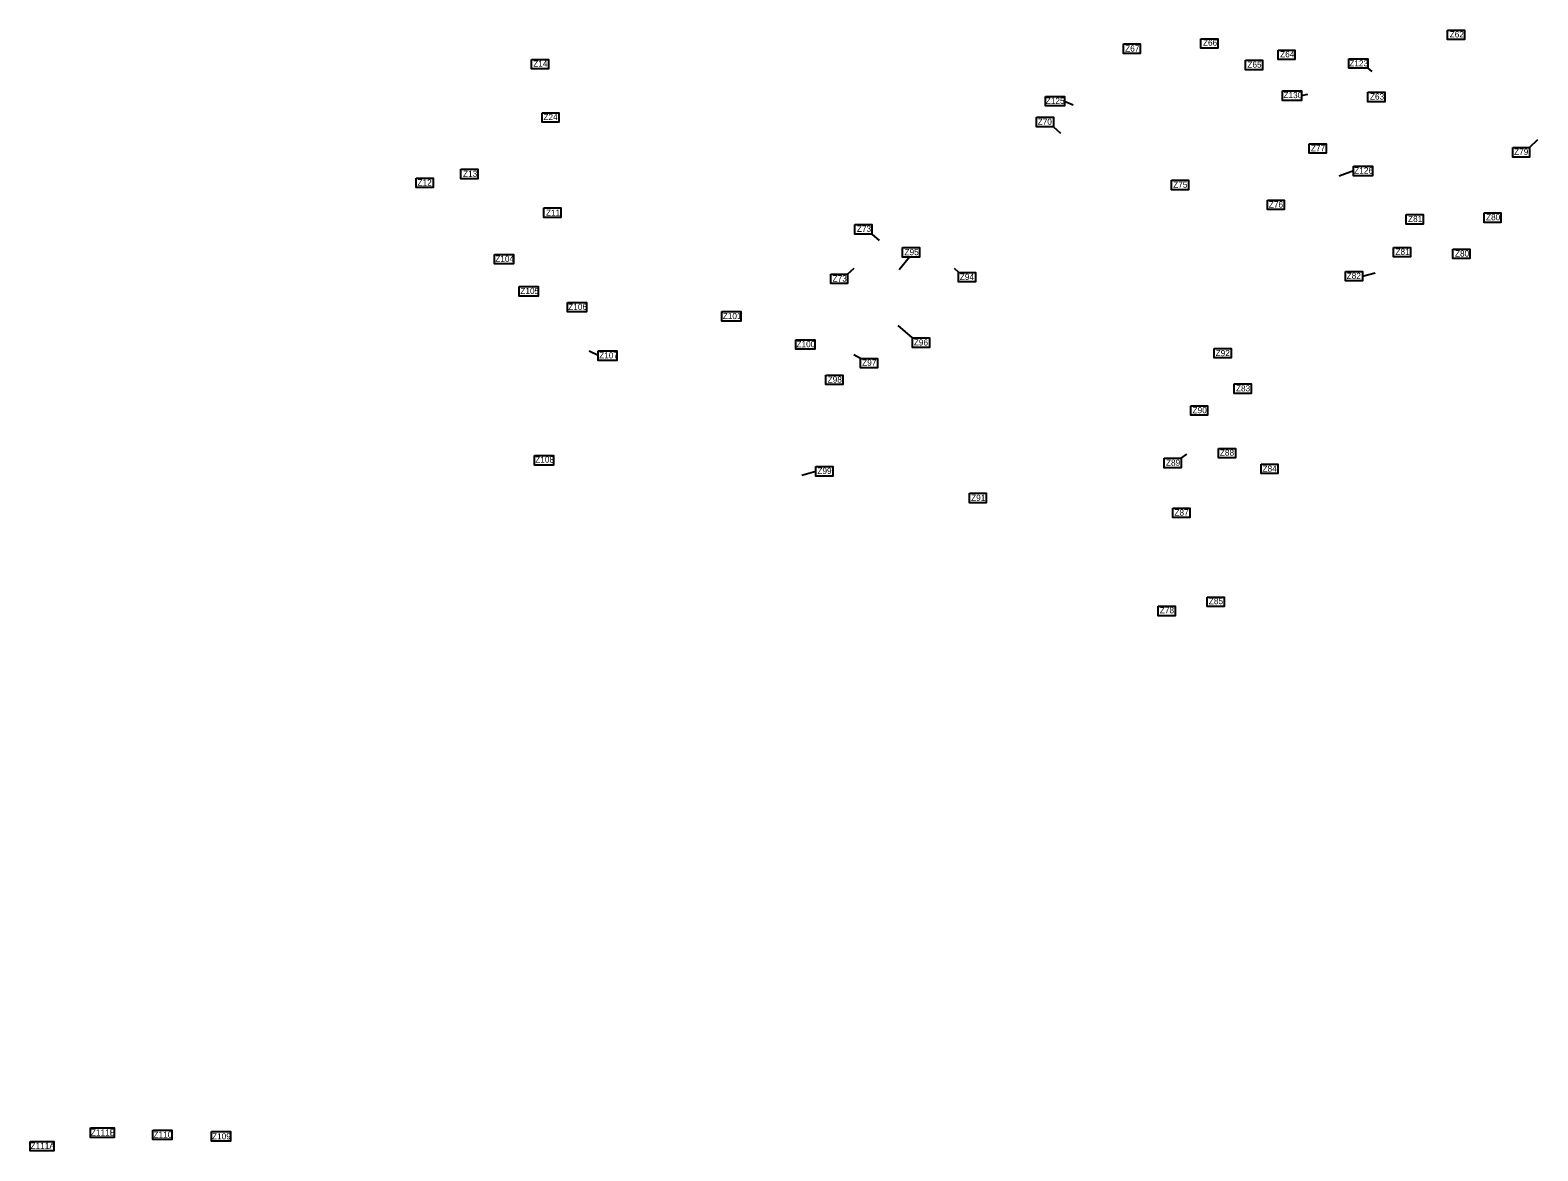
# Model space of a CAD drawing. Extents: x -443485 to -434416, y -1135265 to -1129797.
# Drawn here: x -443485 to -441040, y -1133468 to -1131650 of the extents above; entities that cross this region are included whole.
import ezdxf

# ---------------------------------------------------------------- set-up
doc = ezdxf.new("R2010")
doc.units = 0
doc.layers.add('Vrstva 3', color=7, linetype='Continuous')
doc.layers.add('Vrstva 8', color=7, linetype='Continuous')

msp = doc.modelspace()

# ---------------------------------------------------------------- linework, layer by layer
at = {"layer": 'Vrstva 3'}
for p, q in [((-441825.2, -1131807.1), (-441813.8, -1131817.4)), ((-441052.9, -1131840.8), (-441039.6, -1131827.8)), ((-442119.8, -1131981.1), (-442108.1, -1131991.8)), ((-442058.5, -1132018.5), (-442075.2, -1132039)), ((-442159, -1132046), (-442148.7, -1132036.3)), ((-441979.2, -1132043), (-441985.6, -1132037)), ((-441324.1, -1132049.4), (-441303.6, -1132044)), ((-442053.6, -1132149.7), (-442077, -1132129.5)), ((-442563.8, -1132178.3), (-442578.2, -1132171.1)), ((-442137.9, -1132182.9), (-442149.2, -1132176.8)), ((-441618.1, -1132344.9), (-441608.8, -1132338.2)), ((-442210.4, -1132366.1), (-442233.5, -1132372.9))]:
    msp.add_line(p, q, dxfattribs=at)
for points in [[(-441186, -1131650.3), (-441158.6, -1131650.3), (-441158.6, -1131665.7), (-441186, -1131665.7)], [(-441711.8, -1131672.7), (-441684.5, -1131672.7), (-441684.5, -1131688.1), (-441711.8, -1131688.1)], [(-441586.1, -1131664.3), (-441558.7, -1131664.3), (-441558.7, -1131679.7), (-441586.1, -1131679.7)], [(-441460.9, -1131682.5), (-441433.5, -1131682.5), (-441433.5, -1131697.9), (-441460.9, -1131697.9)], [(-442671.7, -1131697.8), (-442644.4, -1131697.8), (-442644.4, -1131713.2), (-442671.7, -1131713.2)], [(-441513.5, -1131699.1), (-441486.1, -1131699.1), (-441486.1, -1131714.5), (-441513.5, -1131714.5)], [(-441315.3, -1131751.1), (-441287.9, -1131751.1), (-441287.9, -1131766.5), (-441315.3, -1131766.5)], [(-442654.5, -1131784.2), (-442627.2, -1131784.2), (-442627.2, -1131799.6), (-442654.5, -1131799.6)], [(-441852.6, -1131791.7), (-441825.2, -1131791.7), (-441825.2, -1131807.1), (-441852.6, -1131807.1)], [(-441410.4, -1131834.5), (-441383, -1131834.5), (-441383, -1131849.9), (-441410.4, -1131849.9)], [(-441080.2, -1131840.8), (-441052.9, -1131840.8), (-441052.9, -1131856.2), (-441080.2, -1131856.2)], [(-442786.3, -1131876), (-442759, -1131876), (-442759, -1131891.4), (-442786.3, -1131891.4)], [(-442858.8, -1131890.4), (-442831.4, -1131890.4), (-442831.4, -1131905.8), (-442858.8, -1131905.8)], [(-441633.7, -1131893.9), (-441606.4, -1131893.9), (-441606.4, -1131909.3), (-441633.7, -1131909.3)], [(-441478.3, -1131925.9), (-441450.9, -1131925.9), (-441450.9, -1131941.3), (-441478.3, -1131941.3)], [(-442651.8, -1131938.6), (-442624.4, -1131938.6), (-442624.4, -1131954), (-442651.8, -1131954)], [(-441253, -1131949.4), (-441225.6, -1131949.4), (-441225.6, -1131964.8), (-441253, -1131964.8)], [(-441126.7, -1131946.9), (-441099.4, -1131946.9), (-441099.4, -1131962.3), (-441126.7, -1131962.3)], [(-442147.2, -1131965.7), (-442119.8, -1131965.7), (-442119.8, -1131981.1), (-442147.2, -1131981.1)], [(-441273.5, -1132002.7), (-441246.1, -1132002.7), (-441246.1, -1132018.1), (-441273.5, -1132018.1)], [(-442731.9, -1132014.2), (-442701.2, -1132014.2), (-442701.2, -1132029.6), (-442731.9, -1132029.6)], [(-442069.8, -1132003.1), (-442042.5, -1132003.1), (-442042.5, -1132018.5), (-442069.8, -1132018.5)], [(-441177.4, -1132005.6), (-441150, -1132005.6), (-441150, -1132021), (-441177.4, -1132021)], [(-442186.4, -1132046), (-442159, -1132046), (-442159, -1132061.4), (-442186.4, -1132061.4)], [(-441979.2, -1132043.3), (-441951.9, -1132043.3), (-441951.9, -1132058.7), (-441979.2, -1132058.7)], [(-441351.4, -1132041.7), (-441324.1, -1132041.7), (-441324.1, -1132057.1), (-441351.4, -1132057.1)], [(-442691.5, -1132066.2), (-442660.7, -1132066.2), (-442660.7, -1132081.6), (-442691.5, -1132081.6)], [(-442613.5, -1132092), (-442582.8, -1132092), (-442582.8, -1132107.4), (-442613.5, -1132107.4)], [(-442363, -1132106.9), (-442332.2, -1132106.9), (-442332.2, -1132122.3), (-442363, -1132122.3)], [(-442563.8, -1132170.6), (-442533.1, -1132170.6), (-442533.1, -1132186), (-442563.8, -1132186)], [(-442242.9, -1132152.5), (-442212.2, -1132152.5), (-442212.2, -1132167.9), (-442242.9, -1132167.9)], [(-442053.6, -1132149.7), (-442026.2, -1132149.7), (-442026.2, -1132165.1), (-442053.6, -1132165.1)], [(-441564.6, -1132166.6), (-441537.2, -1132166.6), (-441537.2, -1132182), (-441564.6, -1132182)], [(-442137.9, -1132182.9), (-442110.5, -1132182.9), (-442110.5, -1132198.2), (-442137.9, -1132198.2)], [(-442194.3, -1132209.9), (-442166.9, -1132209.9), (-442166.9, -1132225.3), (-442194.3, -1132225.3)], [(-441532.1, -1132224.2), (-441504.8, -1132224.2), (-441504.8, -1132239.6), (-441532.1, -1132239.6)], [(-441602.6, -1132259.7), (-441575.2, -1132259.7), (-441575.2, -1132275.1), (-441602.6, -1132275.1)], [(-442667.1, -1132340.5), (-442636.3, -1132340.5), (-442636.3, -1132355.9), (-442667.1, -1132355.9)], [(-441645.5, -1132344.9), (-441618.1, -1132344.9), (-441618.1, -1132360.3), (-441645.5, -1132360.3)], [(-441557.5, -1132329), (-441530.2, -1132329), (-441530.2, -1132344.4), (-441557.5, -1132344.4)], [(-442210.4, -1132358.4), (-442183, -1132358.4), (-442183, -1132373.8), (-442210.4, -1132373.8)], [(-441488.5, -1132354.4), (-441461.1, -1132354.4), (-441461.1, -1132369.8), (-441488.5, -1132369.8)], [(-441961.6, -1132401.7), (-441934.2, -1132401.7), (-441934.2, -1132417.1), (-441961.6, -1132417.1)], [(-441631.5, -1132425.8), (-441604.1, -1132425.8), (-441604.1, -1132441.2), (-441631.5, -1132441.2)], [(-441655.3, -1132585), (-441627.9, -1132585), (-441627.9, -1132600.4), (-441655.3, -1132600.4)], [(-441575.8, -1132570.2), (-441548.5, -1132570.2), (-441548.5, -1132585.5), (-441575.8, -1132585.5)], [(-443387, -1133431.3), (-443348.5, -1133431.3), (-443348.5, -1133446.7), (-443387, -1133446.7)], [(-443286.1, -1133434.8), (-443255.3, -1133434.8), (-443255.3, -1133450.2), (-443286.1, -1133450.2)], [(-443190.7, -1133437.1), (-443160, -1133437.1), (-443160, -1133452.5), (-443190.7, -1133452.5)], [(-443484.9, -1133453.1), (-443446.5, -1133453.1), (-443446.5, -1133468.5), (-443484.9, -1133468.5)]]:
    msp.add_lwpolyline(points, close=True, dxfattribs=at)
at = {"layer": 'Vrstva 8'}
for p, q in [((-441315.6, -1131712), (-441308.9, -1131717.3)), ((-441422.7, -1131756.5), (-441412.9, -1131754.3)), ((-441807.3, -1131765.5), (-441793.1, -1131771.6)), ((-441338.6, -1131878.7), (-441361.9, -1131887.4))]:
    msp.add_line(p, q, dxfattribs=at)
for points in [[(-441346.4, -1131696.6), (-441315.6, -1131696.6), (-441315.6, -1131712), (-441346.4, -1131712)], [(-441838.1, -1131757.8), (-441807.3, -1131757.8), (-441807.3, -1131773.2), (-441838.1, -1131773.2)], [(-441453.5, -1131748.8), (-441422.7, -1131748.8), (-441422.7, -1131764.2), (-441453.5, -1131764.2)], [(-441338.6, -1131871), (-441307.8, -1131871), (-441307.8, -1131886.4), (-441338.6, -1131886.4)]]:
    msp.add_lwpolyline(points, close=True, dxfattribs=at)

# ---------------------------------------------------------------- texts
at = {"layer": 'Vrstva 3'}
for s, p in [('Z62', (-441182.6, -1131662.1)), ('Z67', (-441708.9, -1131685)), ('Z66', (-441582.7, -1131675.6)), ('Z64', (-441457.5, -1131694.4)), ('Z14', (-442668.9, -1131709.6)), ('Z65', (-441510.7, -1131711.2)), ('Z63', (-441311.9, -1131762.9)), ('Z24', (-442652.4, -1131796.3)), ('Z70', (-441850.8, -1131803.9)), ('Z77', (-441407.6, -1131846.7)), ('Z79', (-441078.1, -1131852.6)), ('Z13', (-442782.8, -1131888.3)), ('Z12', (-442856.6, -1131902.5)), ('Z75', (-441631, -1131906)), ('Z76', (-441475.8, -1131938.1)), ('Z11', (-442648.3, -1131951.5)), ('Z81', (-441250.1, -1131961.6)), ('Z80', (-441123.6, -1131958.7)), ('Z73', (-442144, -1131977.5)), ('Z104', (-442730.5, -1132026.2)), ('Z95', (-442066.8, -1132015.4)), ('Z81', (-441270.5, -1132014.9)), ('Z80', (-441174, -1132017.7)), ('Z73', (-442183.4, -1132058.1)), ('Z94', (-441977.1, -1132055.6)), ('Z82', (-441349.6, -1132054)), ('Z105', (-442689.8, -1132078.4)), ('Z106', (-442612.2, -1132104.3)), ('Z101', (-442361.6, -1132119.1)), ('Z107', (-442562, -1132182.9)), ('Z100', (-442242, -1132164.7)), ('Z96', (-442051.7, -1132161.9)), ('Z92', (-441562.2, -1132179.2)), ('Z97', (-442135.5, -1132194.7)), ('Z98', (-442191.4, -1132222.2)), ('Z83', (-441529.2, -1132236.4)), ('Z90', (-441599.6, -1132271.8)), ('Z108', (-442665.7, -1132352)), ('Z88', (-441555.3, -1132340.8)), ('Z99', (-442208.1, -1132370.3)), ('Z89', (-441642.7, -1132357)), ('Z84', (-441486.1, -1132366.7)), ('Z91', (-441958.8, -1132414.1)), ('Z87', (-441629, -1132437.9)), ('Z78', (-441652.7, -1132596.4)), ('Z85', (-441573.2, -1132581.6)), ('Z111B', (-443386.3, -1133443.6)), ('Z110', (-443284.8, -1133447.1)), ('Z109', (-443189.9, -1133449.9)), ('Z111A', (-443484.3, -1133465.4))]:
    msp.add_text(s, height=10, dxfattribs=at).set_placement(p)
at = {"layer": 'Vrstva 8'}
for s, p in [('Z123', (-441345.4, -1131709.1)), ('Z130', (-441452.2, -1131760.6)), ('Z125', (-441837.7, -1131769.9)), ('Z126', (-441337.4, -1131883))]:
    msp.add_text(s, height=10, dxfattribs=at).set_placement(p)

doc.saveas('drawing.dxf')
